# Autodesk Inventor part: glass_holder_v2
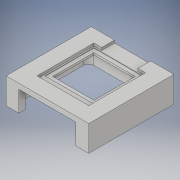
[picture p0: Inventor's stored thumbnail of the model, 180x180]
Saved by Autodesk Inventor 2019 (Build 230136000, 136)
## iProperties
Created: 2019-08
Part Number: glass_holder_v2
Material: 常规
Document SubType Name: Modeling
Designer: YOGA3
Density: 1 g/cm^3
Appearance: 默认
Author: YOGA3
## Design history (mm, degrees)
sketch "草图1"
  geometry: L1 (-16, 16.5)-(16, 16.5); L2 (16, 16.5)-(16, -16.5); L3 (16, -16.5)-(-16, -16.5); L4 (-16, -16.5)-(-16, 16.5); L5 (-16, 16.5)-(16, -16.5); L6 (16, 16.5)-(-16, -16.5); 1 further point
  constraints: 12 end point, 2 midpoint, 2 parallel, 1 horizontal, 1 perpendicular
  dimensions: "d0" = 32 distance of L2.end L3.end; "d1" = 33 distance of L1.end L2.end
extrude "拉伸1" new body sketch "草图1" distance "d2" = 10; taper "d3" = 0 deg
sketch "草图2"
  geometry: L1 (-12.5, 14)-(12.5, 14); L2 (14.5, 12)-(14.5, -12); L3 (12.5, -14)-(-12.5, -14); L4 (-14.5, -12)-(-14.5, 12); L5 (-14.5, 14)-(14.5, -14); L6 (14.5, 14)-(-14.5, -14); A1 r 2 centre (12.5, 12) between (14.5, 12) and (12.5, 14); A2 r 2 centre (-12.5, 12) between (-12.5, 14) and (-14.5, 12); A3 r 2 centre (-12.5, -12) between (-14.5, -12) and (-12.5, -14); A4 r 2 centre (12.5, -12) between (12.5, -14) and (14.5, -12); 1 further point
  constraints: 12 end point, 8 point on circle, 8 point on line, 8 tangent, 4 centre point, 3 equal radius, 2 midpoint, 2 parallel, 1 horizontal, 1 perpendicular
  dimensions: "d4" = 29 distance of L5.end L6.end; "d5" = 28 distance of L6.start L5.end; "d6" = 2 radius of A1 (derived)
extrude "拉伸2" cut sketch "草图2" distance "d7" = 8; taper "d8" = 0 deg
sketch "草图3"
  geometry: L1 (-10, -10.5)-(10, -10.5); L2 (-16, 16.5)-(-16, -16.5) reference; L3 (-16, -16.5)-(16, -16.5) reference; L4 (-7, 16.5)-(-7, 11.5); L5 (-7, 11.5)-(-10, 11.5); L6 (7, 16.5)-(7, 11.5); L7 (7, 11.5)-(10, 11.5); L8 (10, 11.5)-(10, -10.5); L9 (-10, 11.5)-(-10, -10.5); L10 (0, -14)-(0, -16.5); L11 (16, 16.5)-(-16, 16.5) reference; L12 (-7, 16.5)-(7, 16.5); 1 further point
  constraints: 18 end point, 3 point on line, 2 collinear, 2 vertical, 1 horizontal, 1 midpoint, 2 other
  dimensions: "d30" = 14 distance between parallel lines of L6 L4; "d32" = 20 distance between parallel lines of L9 L8; "d33" = 27 distance between parallel lines of L1 L11; "d34" = 5 distance between parallel lines of L11 L5
extrude "拉伸3" cut sketch "草图3" distance "d17" = 1; taper "d18" = 0 deg
sketch "草图4"
  geometry: L1 (-8, 9.5)-(8, 9.5); L2 (8, 9.5)-(8, -6.5); L3 (8, -6.5)-(-8, -6.5); L4 (-8, -6.5)-(-8, 9.5); L5 (-8, 9.5)-(8, -6.5); L6 (8, 9.5)-(-8, -6.5); L7 (-10, -10.5)-(-10, 11.5) reference; L8 (0, 1.5)-(0, 0); 2 further points; 1 other entity
  constraints: 14 end point, 2 midpoint, 2 parallel, 1 horizontal, 1 perpendicular, 1 other
  dimensions: "d19" = 16 distance of L2.end L3.end; "d20" = 16 distance of L1.end L2.end; "d21" = 4 dimension on L3; "d35" = 2 distance between parallel lines of L7 L4
extrude "拉伸4" cut sketch "草图4" distance "d22" = 3; taper "d23" = 0 deg
sketch "草图5"
  geometry: L1 (25, 8)-(0, 8) reference; L2 (23.5, -8)-(1.5, -8); L3 (1.5, -8)-(1.5, 8); L4 (1.5, 8)-(23.5, 8); L5 (23.5, 8)-(23.5, -8); L6 (23.5, -8)-(1.5, 8); L7 (1.5, -8)-(23.5, 8); 1 further point
  constraints: 12 end point, 2 midpoint, 2 parallel, 1 horizontal, 1 perpendicular, 1 point on line
  dimensions: "d24" = 22 distance of L3.end L4.end
extrude "拉伸5" cut sketch "草图5" distance "d25" = 3; taper "d26" = 0 deg
sketch "Sketch7"
  geometry: L1 (-9.5, -8)-(9.5, -8); L2 (9.5, -8)-(9.5, 11); L3 (9.5, 11)-(-9.5, 11); L4 (-9.5, 11)-(-9.5, -8); L5 (-8, 9.5)-(8, 9.5) reference; L6 (8, -6.5)-(-8, -6.5) reference; L7 (-8, -6.5)-(-8, 9.5) reference; L8 (8, 9.5)-(8, -6.5) reference; 1 further point
  constraints: 8 end point, 2 parallel, 1 horizontal, 1 perpendicular
  dimensions: "d36" = 1.5 distance between parallel lines of L5 L3; "d37" = 1.5 distance between parallel lines of L1 L6; "d38" = 1.5 distance between parallel lines of L7 L4; "d39" = 1.5 distance between parallel lines of L8 L2
extrude "Extrusion7" cut sketch "Sketch7" distance "d40" = 0.2; taper "d41" = 0 deg
sketch "草图6"
  geometry: L1 (20.282, -42.755)-(-20.282, -42.755); L2 (-20.282, -42.755)-(-20.282, 42.755); L3 (-20.282, 42.755)-(20.282, 42.755); L4 (20.282, 42.755)-(20.282, -42.755); L5 (20.282, -42.755)-(-20.282, 42.755); L6 (-20.282, -42.755)-(20.282, 42.755); 1 further point
  constraints: 12 end point, 2 midpoint, 2 parallel, 1 horizontal, 1 perpendicular
extrude "拉伸6" cut sketch "草图6" distance "d27" = 1; taper "d28" = 0 deg
node "实体1"
